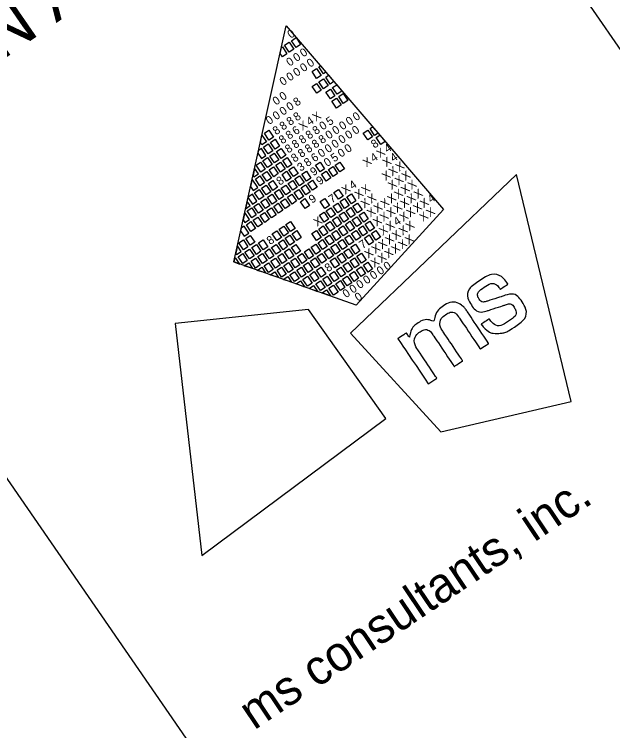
# Model space of a CAD drawing. Extents: x 2200598 to 2206607, y 633643 to 637565.
# Drawn here: x 2204275.6 to 2204395.6, y 635710.6 to 635854.3 of the extents above; entities that cross this region are included whole.
import ezdxf

# ---------------------------------------------------------------- set-up
doc = ezdxf.new("R2010")
doc.units = 0
for name, color, linetype in [('Default', 7, 'Continuous'), ('RW_X_CL_100_Cardinal_Points', 7, 'Continuous'), ('RW_X_CL_100_Curve_Data', 7, 'Continuous')]:
    doc.layers.add(name, color=color, linetype=linetype)

msp = doc.modelspace()

# ---------------------------------------------------------------- linework, layer by layer
at = {"layer": 'Default'}
for p, q in [((2204319.6, 635804.64), (2204330.13, 635851.96)), ((2204330.13, 635851.96), (2204330.13, 635851.96)), ((2204330.13, 635851.96), (2204361.64, 635815.19)), ((2204361.64, 635815.19), (2204344.16, 635795.96)), ((2204344.16, 635795.96), (2204319.6, 635804.64))]:
    msp.add_line(p, q, dxfattribs=at)
for points in [[(2204329.8, 635848.09), (2204330.71, 635848.7), (2204331.63, 635847.33), (2204330.72, 635846.72)], [(2204331.17, 635849.01), (2204332.08, 635849.62), (2204333, 635848.25), (2204332.09, 635847.64)], [(2204328.91, 635846.46), (2204329.18, 635847.67), (2204329.34, 635847.78), (2204330.26, 635846.41), (2204329.35, 635845.8)], [(2204336.65, 635843.74), (2204336.99, 635843.96), (2204338.07, 635842.7), (2204337.57, 635842.37)], [(2204335.29, 635842.82), (2204336.2, 635843.44), (2204337.12, 635842.06), (2204336.21, 635841.45)], [(2204336.67, 635840.76), (2204337.58, 635841.38), (2204338.5, 635840.01), (2204337.59, 635839.39)], [(2204338.03, 635841.68), (2204338.61, 635842.07), (2204339.69, 635840.81), (2204338.95, 635840.31)], [(2204335.3, 635839.85), (2204336.21, 635840.46), (2204337.13, 635839.09), (2204336.22, 635838.48)], [(2204339.42, 635839.63), (2204340.23, 635840.17), (2204340.89, 635839.4), (2204341.25, 635838.87), (2204340.34, 635838.26)], [(2204338.05, 635838.71), (2204338.96, 635839.32), (2204339.88, 635837.95), (2204338.97, 635837.34)], [(2204340.64, 635837.8), (2204341.56, 635838.41), (2204342.48, 635837.04), (2204341.56, 635836.43)], [(2204339.28, 635836.88), (2204340.19, 635837.49), (2204341.11, 635836.12), (2204340.2, 635835.51)], [(2204325.74, 635830.44), (2204326.65, 635831.05), (2204327.57, 635829.68), (2204326.66, 635829.07)], [(2204345.55, 635830.49), (2204346.47, 635831.1), (2204347.39, 635829.73), (2204346.47, 635829.12)], [(2204346.92, 635831.41), (2204347.44, 635831.76), (2204348.52, 635830.49), (2204347.84, 635830.03)], [(2204324.93, 635828.6), (2204325.26, 635830.08), (2204326.16, 635828.74), (2204325.25, 635828.13)], [(2204348.15, 635829.58), (2204348.88, 635830.07), (2204349.97, 635828.81), (2204349.07, 635828.21)], [(2204325.59, 635827.69), (2204326.51, 635828.31), (2204327.43, 635826.93), (2204326.51, 635826.32)], [(2204326.96, 635828.61), (2204327.88, 635829.23), (2204328.8, 635827.85), (2204327.88, 635827.24)], [(2204328.19, 635826.78), (2204329.1, 635827.4), (2204330.02, 635826.03), (2204329.11, 635825.41)], [(2204325.45, 635824.94), (2204326.36, 635825.56), (2204327.28, 635824.19), (2204326.37, 635823.57)], [(2204326.82, 635825.86), (2204327.73, 635826.48), (2204328.65, 635825.11), (2204327.74, 635824.49)], [(2204329.42, 635824.96), (2204330.33, 635825.57), (2204331.25, 635824.2), (2204330.34, 635823.59)], [(2204324.08, 635824.02), (2204324.99, 635824.64), (2204325.91, 635823.27), (2204325, 635822.65)], [(2204328.05, 635824.04), (2204328.96, 635824.65), (2204329.88, 635823.28), (2204328.97, 635822.66)], [(2204335.99, 635824.06), (2204336.9, 635824.68), (2204337.82, 635823.31), (2204336.91, 635822.69)], [(2204339.94, 635824.07), (2204340.86, 635824.68), (2204341.78, 635823.31), (2204340.86, 635822.7)], [(2204325.3, 635822.19), (2204326.22, 635822.81), (2204327.14, 635821.44), (2204326.23, 635820.82)], [(2204326.68, 635823.11), (2204327.59, 635823.73), (2204328.51, 635822.36), (2204327.6, 635821.74)], [(2204329.27, 635822.21), (2204330.19, 635822.82), (2204331.11, 635821.45), (2204330.19, 635820.84)], [(2204330.65, 635823.13), (2204331.56, 635823.74), (2204332.48, 635822.37), (2204331.57, 635821.76)], [(2204333.24, 635822.22), (2204334.16, 635822.83), (2204335.08, 635821.46), (2204334.16, 635820.85)], [(2204337.21, 635822.23), (2204338.13, 635822.85), (2204339.05, 635821.48), (2204338.13, 635820.86)], [(2204338.58, 635823.16), (2204339.5, 635823.77), (2204340.42, 635822.4), (2204339.5, 635821.78)], [(2204323.93, 635821.27), (2204324.85, 635821.89), (2204325.77, 635820.52), (2204324.85, 635819.9)], [(2204326.53, 635820.37), (2204327.45, 635820.98), (2204328.37, 635819.61), (2204327.45, 635819)], [(2204330.5, 635820.38), (2204331.42, 635820.99), (2204332.34, 635819.62), (2204331.42, 635819.01)], [(2204331.87, 635821.3), (2204332.79, 635821.91), (2204333.71, 635820.54), (2204332.79, 635819.93)], [(2204334.47, 635820.39), (2204335.39, 635821.01), (2204336.31, 635819.64), (2204335.39, 635819.02)], [(2204325.16, 635819.45), (2204326.08, 635820.06), (2204327, 635818.69), (2204326.08, 635818.07)], [(2204329.13, 635819.46), (2204330.04, 635820.07), (2204330.97, 635818.7), (2204330.05, 635818.09)], [(2204333.1, 635819.47), (2204334.01, 635820.09), (2204334.93, 635818.72), (2204334.02, 635818.1)], [(2204323.79, 635818.53), (2204324.7, 635819.14), (2204325.63, 635817.77), (2204324.71, 635817.15)], [(2204326.39, 635817.62), (2204327.3, 635818.23), (2204328.22, 635816.86), (2204327.31, 635816.25)], [(2204327.76, 635818.54), (2204328.67, 635819.15), (2204329.59, 635817.78), (2204328.68, 635817.17)], [(2204330.36, 635817.63), (2204331.27, 635818.25), (2204332.19, 635816.87), (2204331.28, 635816.26)], [(2204331.73, 635818.55), (2204332.64, 635819.17), (2204333.56, 635817.79), (2204332.65, 635817.18)], [(2204339.67, 635818.58), (2204340.58, 635819.19), (2204341.5, 635817.82), (2204340.59, 635817.21)], [(2204342.27, 635817.67), (2204343.18, 635818.29), (2204344.1, 635816.91), (2204343.19, 635816.3)], [(2204325.02, 635816.7), (2204325.93, 635817.31), (2204326.85, 635815.94), (2204325.94, 635815.33)], [(2204328.99, 635816.71), (2204329.9, 635817.32), (2204330.82, 635815.95), (2204329.91, 635815.34)], [(2204332.96, 635816.72), (2204333.87, 635817.34), (2204334.79, 635815.97), (2204333.88, 635815.35)], [(2204336.93, 635816.74), (2204337.84, 635817.35), (2204338.76, 635815.98), (2204337.85, 635815.37)], [(2204340.9, 635816.75), (2204341.81, 635817.36), (2204342.73, 635815.99), (2204341.82, 635815.38)], [(2204322.28, 635814.86), (2204323.19, 635815.47), (2204324.11, 635814.1), (2204323.2, 635813.48)], [(2204323.65, 635815.78), (2204324.56, 635816.39), (2204325.48, 635815.02), (2204324.57, 635814.41)], [(2204326.25, 635814.87), (2204327.16, 635815.48), (2204328.08, 635814.11), (2204327.17, 635813.5)], [(2204327.62, 635815.79), (2204328.53, 635816.4), (2204329.45, 635815.03), (2204328.54, 635814.42)], [(2204338.15, 635814.91), (2204339.07, 635815.52), (2204339.99, 635814.15), (2204339.07, 635813.54)], [(2204339.52, 635815.83), (2204340.44, 635816.44), (2204341.36, 635815.07), (2204340.45, 635814.46)], [(2204342.12, 635814.92), (2204343.04, 635815.54), (2204343.96, 635814.17), (2204343.04, 635813.55)], [(2204343.49, 635815.84), (2204344.41, 635816.46), (2204345.33, 635815.09), (2204344.41, 635814.47)], [(2204324.87, 635813.95), (2204325.79, 635814.56), (2204326.71, 635813.19), (2204325.8, 635812.58)], [(2204336.78, 635813.99), (2204337.7, 635814.6), (2204338.62, 635813.23), (2204337.7, 635812.62)], [(2204340.75, 635814), (2204341.67, 635814.62), (2204342.59, 635813.25), (2204341.67, 635812.63)], [(2204344.72, 635814.02), (2204345.64, 635814.63), (2204346.56, 635813.26), (2204345.64, 635812.64)], [(2204322.13, 635812.11), (2204323.05, 635812.72), (2204323.97, 635811.35), (2204323.05, 635810.74)], [(2204323.5, 635813.03), (2204324.42, 635813.64), (2204325.34, 635812.27), (2204324.42, 635811.66)], [(2204330.07, 635812.13), (2204330.99, 635812.75), (2204331.91, 635811.38), (2204330.99, 635810.76)], [(2204338.01, 635812.16), (2204338.92, 635812.77), (2204339.84, 635811.4), (2204338.93, 635810.79)], [(2204339.38, 635813.08), (2204340.3, 635813.7), (2204341.22, 635812.32), (2204340.3, 635811.71)], [(2204341.98, 635812.17), (2204342.89, 635812.79), (2204343.81, 635811.42), (2204342.9, 635810.8)], [(2204343.35, 635813.09), (2204344.26, 635813.71), (2204345.19, 635812.34), (2204344.27, 635811.72)], [(2204345.95, 635812.19), (2204346.86, 635812.8), (2204347.78, 635811.43), (2204346.87, 635810.82)], [(2204327.33, 635810.29), (2204328.24, 635810.91), (2204329.16, 635809.54), (2204328.25, 635808.92)], [(2204328.7, 635811.21), (2204329.61, 635811.83), (2204330.54, 635810.46), (2204329.62, 635809.84)], [(2204331.3, 635810.31), (2204332.21, 635810.92), (2204333.13, 635809.55), (2204332.22, 635808.94)], [(2204335.27, 635810.32), (2204336.18, 635810.93), (2204337.1, 635809.56), (2204336.19, 635808.95)], [(2204336.64, 635811.24), (2204337.55, 635811.85), (2204338.47, 635810.48), (2204337.56, 635809.87)], [(2204339.24, 635810.33), (2204340.15, 635810.95), (2204341.07, 635809.58), (2204340.16, 635808.96)], [(2204340.61, 635811.25), (2204341.52, 635811.87), (2204342.44, 635810.5), (2204341.53, 635809.88)], [(2204343.21, 635810.35), (2204344.12, 635810.96), (2204345.04, 635809.59), (2204344.13, 635808.98)], [(2204344.58, 635811.27), (2204345.49, 635811.88), (2204346.41, 635810.51), (2204345.5, 635809.9)], [(2204347.18, 635810.36), (2204348.09, 635810.97), (2204349.01, 635809.6), (2204348.1, 635808.99)], [(2204321.99, 635809.36), (2204322.9, 635809.97), (2204323.82, 635808.6), (2204322.91, 635807.99)], [(2204329.93, 635809.39), (2204330.84, 635810), (2204331.76, 635808.63), (2204330.85, 635808.01)], [(2204337.87, 635809.41), (2204338.78, 635810.03), (2204339.7, 635808.66), (2204338.79, 635808.04)], [(2204341.84, 635809.43), (2204342.75, 635810.04), (2204343.67, 635808.67), (2204342.76, 635808.05)], [(2204345.81, 635809.44), (2204346.72, 635810.05), (2204347.64, 635808.68), (2204346.73, 635808.07)], [(2204320.62, 635808.44), (2204321.53, 635809.05), (2204322.45, 635807.68), (2204321.54, 635807.07)], [(2204323.22, 635807.53), (2204324.13, 635808.14), (2204325.05, 635806.77), (2204324.14, 635806.16)], [(2204324.59, 635808.45), (2204325.5, 635809.07), (2204326.42, 635807.69), (2204325.51, 635807.08)], [(2204327.19, 635807.54), (2204328.1, 635808.16), (2204329.02, 635806.79), (2204328.11, 635806.17)], [(2204328.56, 635808.46), (2204329.47, 635809.08), (2204330.39, 635807.71), (2204329.48, 635807.09)], [(2204331.16, 635807.56), (2204332.07, 635808.17), (2204332.99, 635806.8), (2204332.08, 635806.19)], [(2204335.13, 635807.57), (2204336.04, 635808.18), (2204336.96, 635806.81), (2204336.05, 635806.2)], [(2204336.5, 635808.49), (2204337.41, 635809.11), (2204338.33, 635807.73), (2204337.42, 635807.12)], [(2204339.09, 635807.58), (2204340.01, 635808.2), (2204340.93, 635806.83), (2204340.02, 635806.21)], [(2204340.47, 635808.51), (2204341.38, 635809.12), (2204342.3, 635807.75), (2204341.39, 635807.13)], [(2204343.06, 635807.6), (2204343.98, 635808.21), (2204344.9, 635806.84), (2204343.98, 635806.23)], [(2204321.85, 635806.61), (2204322.76, 635807.22), (2204323.68, 635805.85), (2204322.77, 635805.24)], [(2204325.82, 635806.62), (2204326.73, 635807.24), (2204327.65, 635805.87), (2204326.74, 635805.25)], [(2204329.78, 635806.64), (2204330.7, 635807.25), (2204331.62, 635805.88), (2204330.71, 635805.27)], [(2204333.75, 635806.65), (2204334.67, 635807.26), (2204335.59, 635805.89), (2204334.67, 635805.28)], [(2204337.72, 635806.66), (2204338.64, 635807.28), (2204339.56, 635805.91), (2204338.64, 635805.29)], [(2204341.69, 635806.68), (2204342.61, 635807.29), (2204343.53, 635805.92), (2204342.61, 635805.31)], [(2204320.48, 635805.69), (2204321.39, 635806.3), (2204322.31, 635804.93), (2204321.4, 635804.32)], [(2204323.07, 635804.78), (2204323.99, 635805.4), (2204324.91, 635804.03), (2204323.99, 635803.41)], [(2204324.44, 635805.7), (2204325.36, 635806.32), (2204326.28, 635804.95), (2204325.37, 635804.33)], [(2204327.04, 635804.8), (2204327.96, 635805.41), (2204328.88, 635804.04), (2204327.96, 635803.42)], [(2204328.41, 635805.72), (2204329.33, 635806.33), (2204330.25, 635804.96), (2204329.33, 635804.35)], [(2204331.01, 635804.81), (2204331.93, 635805.42), (2204332.85, 635804.05), (2204331.93, 635803.44)], [(2204332.38, 635805.73), (2204333.3, 635806.34), (2204334.22, 635804.97), (2204333.3, 635804.36)], [(2204334.98, 635804.82), (2204335.9, 635805.44), (2204336.82, 635804.07), (2204335.9, 635803.45)], [(2204336.35, 635805.74), (2204337.27, 635806.36), (2204338.19, 635804.99), (2204337.27, 635804.37)], [(2204338.95, 635804.84), (2204339.86, 635805.45), (2204340.79, 635804.08), (2204339.87, 635803.47)], [(2204340.32, 635805.76), (2204341.24, 635806.37), (2204342.16, 635805), (2204341.24, 635804.39)], [(2204342.92, 635804.85), (2204343.83, 635805.46), (2204344.75, 635804.09), (2204343.84, 635803.48)], [(2204344.29, 635805.77), (2204345.21, 635806.38), (2204346.13, 635805.01), (2204345.21, 635804.4)], [(2204321.7, 635803.86), (2204322.62, 635804.48), (2204323.38, 635803.33)], [(2204325.67, 635803.88), (2204326.59, 635804.49), (2204327.51, 635803.12), (2204326.59, 635802.5)], [(2204329.64, 635803.89), (2204330.56, 635804.5), (2204331.48, 635803.13), (2204330.56, 635802.52)], [(2204333.61, 635803.9), (2204334.52, 635804.52), (2204335.45, 635803.14), (2204334.53, 635802.53)], [(2204341.55, 635803.93), (2204342.46, 635804.54), (2204343.38, 635803.17), (2204342.47, 635802.56)], [(2204344.2, 635803.06), (2204345.12, 635803.67), (2204346.04, 635802.3), (2204345.12, 635801.69)], [(2204345.59, 635803.99), (2204346.5, 635804.6), (2204347.42, 635803.23), (2204346.51, 635802.62)], [(2204324.3, 635802.95), (2204325.21, 635803.57), (2204325.98, 635802.43)], [(2204326.9, 635802.05), (2204327.81, 635802.66), (2204328.58, 635801.52)], [(2204327.81, 635802.66), (2204327.81, 635802.66), (2204327.81, 635802.66)], [(2204328.27, 635802.97), (2204329.18, 635803.58), (2204330.11, 635802.21), (2204329.19, 635801.6)], [(2204330.87, 635802.06), (2204331.78, 635802.67), (2204332.7, 635801.3), (2204331.79, 635800.69)], [(2204332.24, 635802.98), (2204333.15, 635803.6), (2204334.07, 635802.22), (2204333.16, 635801.61)], [(2204334.84, 635802.07), (2204335.75, 635802.69), (2204336.67, 635801.32), (2204335.76, 635800.7)], [(2204336.21, 635802.99), (2204337.12, 635803.61), (2204338.04, 635802.24), (2204337.13, 635801.62)], [(2204338.81, 635802.09), (2204339.72, 635802.7), (2204340.64, 635801.33), (2204339.73, 635800.72)], [(2204340.18, 635803.01), (2204341.09, 635803.62), (2204342.01, 635802.25), (2204341.1, 635801.64)], [(2204342.8, 635802.12), (2204343.71, 635802.73), (2204344.63, 635801.36), (2204343.72, 635800.75)], [(2204329.5, 635801.14), (2204330.41, 635801.75), (2204331.18, 635800.61)], [(2204333.86, 635799.59), (2204332.08, 635800.23), (2204333.01, 635800.85)], [(2204333.47, 635801.15), (2204334.38, 635801.77), (2204335.3, 635800.4), (2204334.39, 635799.78)], [(2204336.07, 635800.25), (2204336.98, 635800.86), (2204337.9, 635799.49), (2204336.99, 635798.88)], [(2204337.44, 635801.17), (2204338.35, 635801.78), (2204339.27, 635800.41), (2204338.36, 635799.8)], [(2204340.05, 635800.28), (2204340.97, 635800.89), (2204341.89, 635799.52), (2204340.97, 635798.91)], [(2204341.41, 635801.19), (2204342.32, 635801.8), (2204343.25, 635800.43), (2204342.33, 635799.82)], [(2204336.45, 635798.64), (2204334.69, 635799.33), (2204335.6, 635799.94)], [(2204338.67, 635799.35), (2204339.58, 635799.96), (2204340.5, 635798.59), (2204339.59, 635797.98)], [(2204337.33, 635798.45), (2204338.2, 635799.04), (2204339, 635797.86)]]:
    msp.add_lwpolyline(points, close=True, dxfattribs=at)
for points in [[(2204325.13, 635827.38), (2204324.58, 635827.01), (2204324.45, 635826.43), (2204325.14, 635825.4), (2204326.06, 635826.01), (2204325.13, 635827.38)], [(2204323.79, 635823.46), (2204323.46, 635821.98), (2204323.63, 635821.73), (2204324.54, 635822.34), (2204323.79, 635823.46)], [(2204323.3, 635821.24), (2204322.96, 635819.75), (2204323.48, 635818.98), (2204324.4, 635819.6), (2204323.3, 635821.24)], [(2204387.25, 635776.62), (2204376.29, 635822.17), (2204343.02, 635790.37), (2204361.09, 635770.6), (2204387.25, 635776.62)], [(2204323.33, 635818.22), (2204322.5, 635817.66), (2204322.47, 635817.53), (2204323.34, 635816.23), (2204324.25, 635816.85), (2204323.33, 635818.22)], [(2204322.3, 635816.79), (2204321.98, 635815.32), (2204322.88, 635815.93), (2204322.3, 635816.79)], [(2204321.81, 635814.56), (2204321.48, 635813.08), (2204321.83, 635812.56), (2204322.74, 635813.18), (2204321.81, 635814.56)], [(2204321.68, 635811.8), (2204321.11, 635811.42), (2204320.98, 635810.85), (2204321.68, 635809.82), (2204322.6, 635810.43), (2204321.68, 635811.8)], [(2204320.32, 635807.89), (2204319.99, 635806.4), (2204320.17, 635806.15), (2204321.08, 635806.76), (2204320.32, 635807.89)], [(2204320.02, 635805.38), (2204319.72, 635805.19), (2204319.6, 635804.64), (2204320.8, 635804.22), (2204320.02, 635805.38)], [(2204307.86, 635792.29), (2204313.18, 635745.75), (2204350.08, 635773.26), (2204334.56, 635795.08), (2204307.86, 635792.29)]]:
    msp.add_lwpolyline(points, dxfattribs=at)
for points in [[(2204369.24, 635792.07), (2204369.24, 635792.07), (2204369.19, 635792.14), (2204369.19, 635792.14), (2204369.19, 635792.14), (2204369.26, 635792.18), (2204369.26, 635792.18), (2204369.26, 635792.18), (2204370.75, 635793.18), (2204370.75, 635793.18), (2204370.75, 635793.18), (2204370.8, 635793.22), (2204370.8, 635793.22), (2204370.8, 635793.22), (2204370.85, 635793.17), (2204370.85, 635793.17), (2204371.82, 635791.94), (2204373.05, 635791.63), (2204374.73, 635792.76), (2204376.25, 635793.78), (2204376.22, 635794.9), (2204375.8, 635795.54), (2204375.24, 635796.38), (2204374.45, 635796.16), (2204373.65, 635795.9), (2204373.65, 635795.9), (2204370.63, 635794.92), (2204370.63, 635794.92), (2204369.16, 635794.43), (2204367.95, 635794.94), (2204367.26, 635795.96), (2204366.36, 635797.3), (2204366.47, 635799.28), (2204368.83, 635800.87), (2204371.29, 635802.52), (2204373.45, 635801.84), (2204374.51, 635800.26), (2204374.51, 635800.26), (2204374.55, 635800.2), (2204374.55, 635800.2), (2204374.55, 635800.2), (2204374.49, 635800.16), (2204374.49, 635800.16), (2204374.49, 635800.16), (2204373.08, 635799.21), (2204373.08, 635799.21), (2204373.08, 635799.21), (2204373.02, 635799.17), (2204373.02, 635799.17), (2204373.02, 635799.17), (2204372.98, 635799.23), (2204372.98, 635799.23), (2204372.32, 635800.16), (2204371.18, 635800.5), (2204369.77, 635799.54), (2204368.4, 635798.63), (2204368.45, 635797.68), (2204368.79, 635797.17), (2204369.07, 635796.76), (2204369.55, 635796.51), (2204370.45, 635796.79), (2204370.45, 635796.79), (2204373.38, 635797.74), (2204373.38, 635797.74), (2204375.43, 635798.4), (2204376.59, 635797.83), (2204377.36, 635796.69), (2204378.35, 635795.22), (2204378.29, 635793.21), (2204375.61, 635791.41), (2204374.48, 635790.65), (2204373.74, 635790.42), (2204373.14, 635790.35), (2204371.67, 635790.16), (2204370.32, 635790.71), (2204369.24, 635792.07)], [(2204358.59, 635780.18), (2204358.59, 635780.18), (2204352.49, 635789.26), (2204352.49, 635789.26), (2204352.49, 635789.26), (2204354.21, 635790.41), (2204354.21, 635790.41), (2204354.21, 635790.41), (2204354.83, 635789.49), (2204354.83, 635789.49), (2204355.01, 635790.84), (2204355.68, 635791.83), (2204356.5, 635792.38), (2204357.61, 635793.12), (2204358.87, 635793.1), (2204359.83, 635792.47), (2204359.84, 635793.86), (2204360.6, 635795.15), (2204361.56, 635795.8), (2204362.89, 635796.69), (2204364.46, 635796.59), (2204365.59, 635795.69), (2204365.59, 635795.69), (2204365.59, 635795.68), (2204365.6, 635795.68), (2204365.77, 635795.54), (2204365.91, 635795.42), (2204366.48, 635794.58), (2204366.48, 635794.58), (2204370.7, 635788.3), (2204370.7, 635788.3), (2204370.7, 635788.3), (2204369.01, 635787.17), (2204369.01, 635787.17), (2204369.01, 635787.17), (2204364.92, 635793.26), (2204364.92, 635793.26), (2204364.06, 635794.53), (2204362.96, 635794.67), (2204362.06, 635794.06), (2204361.1, 635793.42), (2204360.72, 635791.91), (2204361.66, 635790.51), (2204361.66, 635790.51), (2204365.49, 635784.81), (2204365.49, 635784.81), (2204365.49, 635784.81), (2204363.79, 635783.67), (2204363.79, 635783.67), (2204363.79, 635783.67), (2204359.64, 635789.85), (2204359.64, 635789.85), (2204358.83, 635791.04), (2204357.72, 635791.15), (2204356.96, 635790.64), (2204356.03, 635790.01), (2204355.53, 635788.43), (2204356.69, 635786.7), (2204356.69, 635786.7), (2204360.3, 635781.32), (2204360.3, 635781.32), (2204360.3, 635781.32), (2204358.59, 635780.18), (2204358.59, 635780.18)]]:
    msp.add_open_spline(points, degree=3, dxfattribs=at)
at = {"layer": 'RW_X_CL_100_Cardinal_Points'}
msp.add_line((2204344.65, 635791.11), (2204344.65, 635791.11), dxfattribs=at)
at = {"layer": 'RW_X_CL_100_Curve_Data'}
msp.add_line((2204453.33, 635501.61), (2203260.46, 637229.92), dxfattribs=at)
msp.add_lwpolyline([(2200750.29, 635497.43), (2203383.92, 637315.13), (2204576.78, 635586.81), (2201943.16, 633769.11)], close=True, dxfattribs=at)

# ---------------------------------------------------------------- texts
at = {"layer": 'Default'}
for s, p in [('0', (2204331.02, 635849.38)), ('0', (2204333.54, 635845.63)), ('0', (2204330.8, 635843.79)), ('0', (2204332.17, 635844.71)), ('0', (2204334.92, 635843.57)), ('0', (2204333.55, 635842.65)), ('0', (2204330.82, 635840.81)), ('0', (2204332.18, 635841.73)), ('0', (2204329.45, 635839.9)), ('0', (2204329.43, 635836.9)), ('0', (2204328.06, 635835.98)), ('0', (2204330.82, 635834.85)), ('8', (2204332.21, 635835.78)), ('0', (2204329.45, 635833.93)), ('0', (2204326.7, 635832.08)), ('0', (2204328.07, 635833.01)), ('8', (2204332.22, 635832.81)), ('X', (2204336.08, 635832.74)), ('5', (2204338.78, 635831.9)), ('0', (2204344.11, 635832.83)), ('8', (2204329.45, 635830.95)), ('8', (2204330.85, 635831.89)), ('X', (2204333.34, 635830.91)), ('4', (2204334.82, 635831.9)), ('0', (2204337.42, 635830.98)), ('0', (2204341.38, 635831)), ('0', (2204342.74, 635831.92)), ('8', (2204328.08, 635830.03)), ('8', (2204330.68, 635829.12)), ('6', (2204332, 635830)), ('8', (2204334.68, 635829.15)), ('8', (2204336.05, 635830.06)), ('0', (2204338.64, 635829.16)), ('0', (2204340.01, 635830.08)), ('0', (2204342.6, 635829.17)), ('0', (2204343.97, 635830.09)), ('8', (2204329.31, 635828.2)), ('8', (2204333.31, 635828.23)), ('8', (2204337.27, 635828.24)), ('0', (2204341.24, 635828.25)), ('8', (2204330.54, 635826.37)), ('8', (2204331.91, 635827.29)), ('8', (2204334.54, 635826.4)), ('8', (2204335.91, 635827.32)), ('0', (2204338.5, 635826.41)), ('0', (2204339.87, 635827.33)), ('0', (2204342.46, 635826.42)), ('8', (2204347.79, 635827.35)), ('4', (2204350.39, 635826.44)), ('8', (2204333.13, 635825.46)), ('0', (2204337.13, 635825.5)), ('0', (2204341.1, 635825.51)), ('X', (2204348.91, 635825.45)), ('8', (2204331.76, 635824.54)), ('8', (2204334.36, 635823.64)), ('6', (2204335.76, 635824.58)), ('0', (2204338.33, 635823.65)), ('5', (2204339.72, 635824.58)), ('X', (2204346.18, 635823.61)), ('4', (2204347.65, 635824.6)), ('X', (2204350.14, 635823.62)), ('4', (2204351.61, 635824.61)), ('3', (2204332.99, 635822.72)), ('X', (2204351.37, 635821.79)), ('X', (2204352.73, 635822.71)), ('9', (2204335.59, 635821.81)), ('X', (2204350, 635820.87)), ('X', (2204353.96, 635820.88)), ('8', (2204328.82, 635819.92)), ('9', (2204336.82, 635819.98)), ('4', (2204343.41, 635819.1)), ('X', (2204351.23, 635819.05)), ('X', (2204352.59, 635819.97)), ('X', (2204355.19, 635819.06)), ('X', (2204341.94, 635818.11)), ('X', (2204345.9, 635818.12)), ('X', (2204353.82, 635818.14)), ('9', (2204335.31, 635816.31)), ('7', (2204339.28, 635816.33)), ('X', (2204344.53, 635817.2)), ('X', (2204347.12, 635816.29)), ('X', (2204351.09, 635816.3)), ('X', (2204352.45, 635817.22)), ('X', (2204355.05, 635816.31)), ('X', (2204356.42, 635817.23)), ('4', (2204359.12, 635816.39)), ('X', (2204345.76, 635815.37)), ('X', (2204348.35, 635814.46)), ('X', (2204349.72, 635815.38)), ('X', (2204352.31, 635814.47)), ('X', (2204353.68, 635815.39)), ('X', (2204356.28, 635814.48)), ('X', (2204357.64, 635815.4)), ('X', (2204346.98, 635813.55)), ('X', (2204350.95, 635813.55)), ('X', (2204354.91, 635813.56)), ('X', (2204358.87, 635813.57)), ('X', (2204336.31, 635811.68)), ('X', (2204348.21, 635811.72)), ('X', (2204349.58, 635812.64)), ('X', (2204353.54, 635812.64)), ('X', (2204357.53, 635812.67)), ('X', (2204350.81, 635810.81)), ('4', (2204352.28, 635811.8)), ('X', (2204354.77, 635810.82)), ('X', (2204349.44, 635809.89)), ('X', (2204352.03, 635808.98)), ('X', (2204353.4, 635809.9)), ('8', (2204326.88, 635808)), ('X', (2204350.67, 635808.06)), ('X', (2204354.63, 635808.07)), ('7', (2204345.41, 635807.19)), ('X', (2204347.93, 635806.23)), ('X', (2204349.3, 635807.14)), ('X', (2204351.89, 635806.23)), ('X', (2204353.26, 635807.15)), ('X', (2204346.53, 635805.28)), ('X', (2204349.16, 635804.4)), ('X', (2204350.53, 635805.32)), ('X', (2204347.76, 635803.46)), ('8', (2204338.5, 635802.54)), ('0', (2204348.94, 635801.93)), ('0', (2204350.31, 635802.85)), ('0', (2204347.57, 635801.01)), ('0', (2204344.83, 635799.17)), ('0', (2204346.2, 635800.09)), ('0', (2204343.46, 635798.25)), ('0', (2204342.09, 635797.33)), ('0', (2204344.53, 635796.65))]:
    msp.add_text(s, height=1.65, rotation=33.8833, dxfattribs=at).set_placement(p)
at = {"layer": 'RW_X_CL_100_Cardinal_Points'}
msp.add_text('DESIGN AGENCY', height=10, rotation=34.613, dxfattribs=at).set_placement((2204238.75, 635821.3))
at = {"layer": 'RW_X_CL_100_Curve_Data'}
msp.add_text('ms consultants, inc.', height=7, rotation=33.8833, dxfattribs=at).set_placement((2204323.67, 635710.65))

doc.saveas('drawing.dxf')
